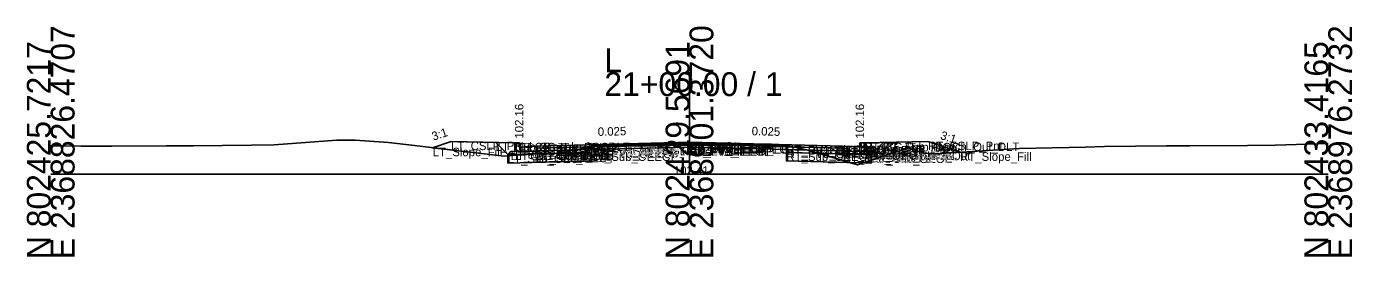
# Model space of a CAD drawing. Extents: x -26 to 8153, y -10 to 9520.
# Drawn here: x 997.2 to 1152.8, y 2490.3 to 2517.3 of the extents above; entities that cross this region are included whole.
import ezdxf

# ---------------------------------------------------------------- set-up
doc = ezdxf.new("R2010")
doc.units = 0
for name, color, linetype in [('Exist CMT Pavement', 7, 'Continuous'), ('Exist Cross Section Cell', 7, 'Continuous'), ('Exist XS Center Line Elevation Label', 7, 'Continuous'), ('Exist XS Ground Line', 7, 'Continuous'), ('Prop CMT Conc Surface', 7, 'Continuous'), ('Prop CMT Concrete Structures', 7, 'Continuous'), ('Prop CMT Pvmt Course 1', 7, 'Continuous'), ('Prop CMT Pvmt Course 1 CG', 7, 'Continuous'), ('Prop CMT Pvmt Course 1 Wedge', 7, 'Continuous'), ('Prop CMT Pvmt Course 2', 7, 'Continuous'), ('Prop CMT Pvmt Course 2 Wedge', 7, 'Continuous'), ('Prop CMT Pvmt Course 3', 7, 'Continuous'), ('Prop CMT Pvmt Course 3 Wedge', 7, 'Continuous'), ('Prop CMT Pvmt Surface', 7, 'Continuous'), ('Prop CMT Pvmt Wedge Surface 1', 7, 'Continuous'), ('Prop CMT Pvmt Wedge Surface 2', 7, 'Continuous'), ('Prop CMT Pvmt Wedge Surface 3', 7, 'Continuous'), ('Prop CMT Shallow Undercut', 7, 'Continuous'), ('Prop CMT Shallow Undercut Boundary', 7, 'Continuous'), ('Prop CMT Slope Grass', 7, 'Continuous'), ('Prop CMT Subgrade Earthwork', 7, 'Continuous'), ('Prop XS Earthwork Shape', 7, 'Continuous'), ('Prop XS Hydro Elevations', 7, 'Continuous'), ('Prop XS SE Text', 7, 'Continuous'), ('Prop XS Side Slope Text', 7, 'Continuous'), ('Prop XS Subgrade Earthwork', 7, 'Continuous'), ('Scratch_Level_2', 7, 'Continuous'), ('Scratch_Level_6', 7, 'Continuous')]:
    doc.layers.add(name, color=color, linetype=linetype)

msp = doc.modelspace()

# ---------------------------------------------------------------- linework, layer by layer
at = {"layer": 'Exist CMT Pavement'}
for p, q in [((1069.64, 2503.31), (1074.61, 2503.41)), ((1074.61, 2503.41), (1075, 2503.41)), ((1075, 2503.41), (1079.57, 2503.41)), ((1079.57, 2503.41), (1086.38, 2503.35)), ((1063.51, 2503.2), (1069.64, 2503.31))]:
    msp.add_line(p, q, dxfattribs=at)
at = {"layer": 'Exist Cross Section Cell'}
for p, q in [((1075, 2500), (1075, 2511.96)), ((1000, 2500), (1075, 2500)), ((1075, 2500), (1150, 2500))]:
    msp.add_line(p, q, dxfattribs=at)
at = {"layer": 'Exist XS Ground Line'}
for p, q in [((1016.71, 2503.33), (1023.59, 2503.4)), ((1023.59, 2503.4), (1026.24, 2503.44)), ((1026.24, 2503.44), (1033.6, 2503.97)), ((1033.6, 2503.97), (1035.76, 2503.99)), ((1035.76, 2503.99), (1039.64, 2503.7)), ((1039.64, 2503.7), (1042.72, 2503.34)), ((1069.64, 2503.31), (1074.61, 2503.41)), ((1074.61, 2503.41), (1075, 2503.41)), ((1075, 2503.41), (1079.57, 2503.41)), ((1079.57, 2503.41), (1086.38, 2503.35)), ((1133.74, 2503.33), (1140.53, 2503.36)), ((1140.53, 2503.36), (1143.75, 2503.41)), ((1143.75, 2503.41), (1150, 2503.57)), ((1000, 2503.32), (1003.56, 2503.26)), ((1003.56, 2503.26), (1007.19, 2503.28)), ((1007.19, 2503.28), (1013.57, 2503.31)), ((1013.57, 2503.31), (1016.71, 2503.33)), ((1042.72, 2503.34), (1049.55, 2502.53)), ((1049.55, 2502.53), (1053.25, 2502.11)), ((1053.25, 2502.11), (1054.73, 2502.22)), ((1054.73, 2502.22), (1057.2, 2502.37)), ((1057.2, 2502.37), (1059.02, 2502.39)), ((1059.02, 2502.39), (1063.51, 2503.2)), ((1063.51, 2503.2), (1069.64, 2503.31)), ((1086.38, 2503.35), (1088.58, 2502.89)), ((1088.58, 2502.89), (1088.89, 2502.82)), ((1088.89, 2502.82), (1090.91, 2502.2)), ((1090.91, 2502.2), (1094.71, 2501.08)), ((1096.79, 2501.78), (1100.77, 2503.08)), ((1100.77, 2503.08), (1101.64, 2502.69)), ((1101.64, 2502.69), (1102.43, 2502.48)), ((1102.43, 2502.48), (1103.7, 2502.38)), ((1103.7, 2502.38), (1105.1, 2502.45)), ((1105.1, 2502.45), (1113.71, 2503)), ((1113.71, 2503), (1121.48, 2503.15)), ((1121.48, 2503.15), (1123.72, 2503.22)), ((1123.72, 2503.22), (1131, 2503.33)), ((1131, 2503.33), (1133.74, 2503.33)), ((1094.71, 2501.08), (1096.79, 2501.78))]:
    msp.add_line(p, q, dxfattribs=at)
at = {"layer": 'Prop CMT Conc Surface'}
for points in [[(1055, 2503.16), (1055, 2503.66), (1054.5, 2503.66)], [(1095, 2503.16), (1095, 2503.66), (1095.5, 2503.66)], [(1057, 2503.29), (1055, 2503.16)], [(1093, 2503.29), (1095, 2503.16)]]:
    msp.add_lwpolyline(points, dxfattribs=at)
at = {"layer": 'Prop CMT Concrete Structures'}
for points in [[(1057, 2503.29), (1055, 2503.16), (1055, 2503.66), (1054.5, 2503.66)], [(1054.5, 2503.66), (1054.5, 2502.64), (1057, 2502.7)], [(1093, 2503.29), (1095, 2503.16), (1095, 2503.66), (1095.5, 2503.66)], [(1095.5, 2503.66), (1095.5, 2502.64), (1093, 2502.7)], [(1057, 2502.7), (1057, 2503.29)], [(1093, 2502.7), (1093, 2503.29)]]:
    msp.add_lwpolyline(points, dxfattribs=at)
at = {"layer": 'Prop CMT Pvmt Course 1'}
for points in [[(1075, 2503.74), (1057, 2503.29)], [(1063.51, 2503.33), (1075, 2503.61)], [(1075, 2503.49), (1075, 2503.74)], [(1075, 2503.74), (1093, 2503.29)], [(1075, 2503.49), (1075, 2503.74)], [(1075, 2503.61), (1075, 2503.49), (1075, 2503.49)], [(1086.38, 2503.33), (1075, 2503.61)], [(1075, 2503.61), (1075, 2503.49), (1075, 2503.49)], [(1057, 2503.29), (1057, 2503.04)], [(1057, 2503.04), (1063.51, 2503.2)], [(1063.51, 2503.2), (1063.51, 2503.33)], [(1086.38, 2503.2), (1086.38, 2503.33)], [(1093, 2503.04), (1086.38, 2503.2)], [(1093, 2503.29), (1093, 2503.04)]]:
    msp.add_lwpolyline(points, dxfattribs=at)
at = {"layer": 'Prop CMT Pvmt Course 1 CG'}
for points in [[(1057, 2502.7), (1054, 2502.63), (1053.66, 2502.29)], [(1053.66, 2502.29), (1057, 2502.38)], [(1057, 2502.38), (1057, 2502.7)], [(1093, 2502.7), (1096, 2502.63), (1096.34, 2502.29)], [(1093, 2502.38), (1093, 2502.7)], [(1096.34, 2502.29), (1093, 2502.38)]]:
    msp.add_lwpolyline(points, dxfattribs=at)
at = {"layer": 'Prop CMT Pvmt Course 1 Wedge'}
for points in [[(1075, 2503.61), (1063.51, 2503.33)], [(1075, 2503.61), (1086.38, 2503.33)]]:
    msp.add_lwpolyline(points, dxfattribs=at)
at = {"layer": 'Prop CMT Pvmt Course 2'}
for points in [[(1063.51, 2503.2), (1057, 2503.04)], [(1057, 2503.04), (1057, 2502.71)], [(1057, 2502.71), (1063.51, 2502.87)], [(1063.51, 2502.87), (1063.51, 2503.2)], [(1086.38, 2502.87), (1086.38, 2503.2)], [(1086.38, 2503.2), (1093, 2503.04)], [(1093, 2502.71), (1086.38, 2502.87)], [(1093, 2503.04), (1093, 2502.71)]]:
    msp.add_lwpolyline(points, dxfattribs=at)
at = {"layer": 'Prop CMT Pvmt Course 2 Wedge'}
for points in [[(1075, 2503.49), (1063.51, 2503.2)], [(1075, 2503.49), (1086.38, 2503.2)]]:
    msp.add_lwpolyline(points, dxfattribs=at)
at = {"layer": 'Prop CMT Pvmt Course 3'}
for points in [[(1063.51, 2502.87), (1057, 2502.71)], [(1057, 2502.71), (1057, 2502.38)], [(1057, 2502.38), (1063.51, 2502.54)], [(1063.51, 2502.54), (1063.51, 2502.87)], [(1086.38, 2502.87), (1093, 2502.71)], [(1086.38, 2502.54), (1086.38, 2502.87)], [(1093, 2502.38), (1086.38, 2502.54)], [(1093, 2502.71), (1093, 2502.38)]]:
    msp.add_lwpolyline(points, dxfattribs=at)
at = {"layer": 'Prop CMT Pvmt Course 3 Wedge'}
for points in [[(1075, 2503.16), (1063.51, 2502.87)], [(1075, 2503.16), (1086.38, 2502.87)]]:
    msp.add_lwpolyline(points, dxfattribs=at)
at = {"layer": 'Prop CMT Pvmt Surface'}
for points in [[(1075, 2503.74), (1057, 2503.29)], [(1075, 2503.74), (1093, 2503.29)]]:
    msp.add_lwpolyline(points, dxfattribs=at)
at = {"layer": 'Prop CMT Pvmt Wedge Surface 1'}
for points in [[(1075, 2503.61), (1063.51, 2503.33)], [(1075, 2503.61), (1086.38, 2503.33)], [(1057, 2503.04), (1057, 2503.29)], [(1063.51, 2503.2), (1057, 2503.04)], [(1063.51, 2503.33), (1063.51, 2503.2)], [(1086.38, 2503.33), (1086.38, 2503.2)], [(1086.38, 2503.2), (1093, 2503.04)], [(1093, 2503.04), (1093, 2503.29)]]:
    msp.add_lwpolyline(points, dxfattribs=at)
at = {"layer": 'Prop CMT Pvmt Wedge Surface 2'}
for points in [[(1075, 2503.49), (1057, 2503.04)], [(1075, 2503.49), (1093, 2503.04)], [(1057, 2503.04), (1057, 2503.29)], [(1093, 2503.04), (1093, 2503.29)]]:
    msp.add_lwpolyline(points, dxfattribs=at)
at = {"layer": 'Prop CMT Pvmt Wedge Surface 3'}
for points in [[(1057, 2502.71), (1057, 2503.29)], [(1075, 2503.16), (1057, 2502.71)], [(1075, 2503.16), (1093, 2502.71)], [(1093, 2502.71), (1093, 2503.29)]]:
    msp.add_lwpolyline(points, dxfattribs=at)
at = {"layer": 'Prop CMT Shallow Undercut'}
for points in [[(1059.02, 2502.39), (1059.27, 2502.43), (1063.51, 2502.54), (1063.51, 2501.54), (1053.66, 2501.29), (1053.66, 2502.14), (1054.73, 2502.22), (1057.2, 2502.37)], [(1086.38, 2502.54), (1086.38, 2501.54), (1093.77, 2501.36), (1090.91, 2502.2), (1090.11, 2502.45)], [(1096.34, 2501.62), (1096.34, 2501.29), (1095.42, 2501.31)]]:
    msp.add_lwpolyline(points, close=True, dxfattribs=at)
at = {"layer": 'Prop CMT Shallow Undercut Boundary'}
for p, q in [((1053.66, 2502.29), (1063.51, 2502.54)), ((1053.66, 2502.29), (1053.66, 2501.29)), ((1063.51, 2502.54), (1063.51, 2501.54)), ((1086.38, 2502.54), (1086.38, 2501.54)), ((1086.38, 2502.54), (1096.34, 2502.29)), ((1096.34, 2502.29), (1096.34, 2501.29)), ((1063.51, 2501.54), (1053.66, 2501.29)), ((1086.38, 2501.54), (1096.34, 2501.29))]:
    msp.add_line(p, q, dxfattribs=at)
at = {"layer": 'Prop CMT Slope Grass'}
for points in [[(1054.5, 2503.66), (1047, 2503.81), (1044.84, 2503.09)], [(1095.5, 2503.66), (1103, 2503.81), (1106.77, 2502.55)]]:
    msp.add_lwpolyline(points, dxfattribs=at)
at = {"layer": 'Prop CMT Subgrade Earthwork'}
for points in [[(1057, 2502.38), (1053.66, 2502.29), (1052.25, 2503.7)], [(1093, 2502.38), (1096.34, 2502.29), (1097.75, 2503.7)], [(1063.51, 2502.54), (1057, 2502.38)], [(1063.51, 2502.54), (1063.53, 2503.2)], [(1086.38, 2502.54), (1086.36, 2503.35)], [(1086.38, 2502.54), (1093, 2502.38)]]:
    msp.add_lwpolyline(points, dxfattribs=at)
at = {"layer": 'Prop XS Earthwork Shape'}
for points in [[(1052.25, 2503.7), (1047, 2503.81), (1044.84, 2503.09), (1049.55, 2502.53), (1053.25, 2502.11), (1053.66, 2502.14), (1053.66, 2502.29)], [(1105.1, 2502.45), (1106.77, 2502.55), (1103, 2503.81), (1097.75, 2503.7), (1096.34, 2502.29), (1096.34, 2501.62), (1096.79, 2501.78), (1100.77, 2503.08), (1101.64, 2502.69), (1102.43, 2502.48), (1103.7, 2502.38)], [(1054.73, 2502.22), (1057.2, 2502.37), (1059.02, 2502.39), (1059.27, 2502.43), (1063.51, 2502.54), (1063.51, 2501.54), (1053.66, 2501.29), (1053.66, 2502.14)], [(1054.73, 2502.22), (1057.2, 2502.37), (1059.02, 2502.39), (1059.27, 2502.43), (1057, 2502.38), (1053.66, 2502.29), (1053.66, 2502.14)], [(1059.27, 2502.43), (1063.51, 2503.2), (1063.53, 2503.2), (1063.51, 2502.54)], [(1086.38, 2503.35), (1088.58, 2502.89), (1088.89, 2502.82), (1090.11, 2502.45), (1086.38, 2502.54), (1086.36, 2503.35)], [(1086.38, 2502.54), (1086.38, 2501.54), (1093.77, 2501.36), (1090.91, 2502.2), (1090.11, 2502.45)], [(1095.42, 2501.31), (1096.34, 2501.62), (1096.34, 2502.29), (1093, 2502.38), (1090.11, 2502.45), (1090.91, 2502.2), (1093.77, 2501.36)], [(1093.77, 2501.36), (1095.42, 2501.31), (1094.71, 2501.08)], [(1095.42, 2501.31), (1096.34, 2501.29), (1096.34, 2501.62)]]:
    msp.add_lwpolyline(points, close=True, dxfattribs=at)
at = {"layer": 'Prop XS Subgrade Earthwork'}
for p, q in [((1053.66, 2502.29), (1063.51, 2502.54)), ((1096.34, 2502.29), (1086.38, 2502.54))]:
    msp.add_line(p, q, dxfattribs=at)
at = {"layer": 'Scratch_Level_6'}
for points in [[(1059.02, 2502.39), (1059.27, 2502.43), (1063.51, 2502.54), (1063.51, 2501.54), (1053.66, 2501.29), (1053.66, 2502.14), (1054.73, 2502.22), (1057.2, 2502.37)], [(1086.38, 2502.54), (1086.38, 2501.54), (1093.77, 2501.36), (1090.91, 2502.2), (1090.11, 2502.45)], [(1096.34, 2501.62), (1096.34, 2501.29), (1095.42, 2501.31)]]:
    msp.add_lwpolyline(points, close=True, dxfattribs=at)

# ---------------------------------------------------------------- texts
at = {"layer": 'Exist Cross Section Cell'}
for s, p in [('E 2368826.4707', (1002.8, 2490)), ('E 2368901.3720', (1077.8, 2490)), ('E 2368976.2732', (1152.8, 2490)), ('N 802425.7217', (1000, 2490)), ('N 802429.5691', (1075, 2490)), ('N 802433.4165', (1150, 2490))]:
    msp.add_text(s, height=2.8, rotation=90, dxfattribs=at).set_placement(p)
for s, p in [('L', (1065, 2511.96)), ('21+00.00 / 1', (1065, 2509.16))]:
    msp.add_text(s, height=2.8, dxfattribs=at).set_placement(p)
at = {"layer": 'Exist XS Center Line Elevation Label'}
msp.add_text('102.41', height=1, dxfattribs=at).set_placement((1073.16, 2499.91))
at = {"layer": 'Prop XS Hydro Elevations'}
for p in [(1055.5, 2504.16), (1095.5, 2504.16)]:
    msp.add_text('102.16', height=1, rotation=90, dxfattribs=at).set_placement(p)
at = {"layer": 'Prop XS SE Text'}
for rotation, p in [(1.4321, (1064.24, 2504.47)), (358.5679, (1082.29, 2504.56))]:
    msp.add_text('0.025', height=1, rotation=rotation, dxfattribs=at).set_placement(p)
at = {"layer": 'Prop XS Side Slope Text'}
for rotation, p in [(18.4349, (1044.93, 2503.91)), (341.5651, (1104.37, 2504.14))]:
    msp.add_text('3:1', height=1, rotation=rotation, dxfattribs=at).set_placement(p)
at = {"layer": 'Scratch_Level_2'}
for s, p in [('LT_CSLP_Pnt', (1047, 2502.81)), ('LT_Sub_Trench_Out_DLT', (1052.25, 2502.7)), ('LT_CG_Top_BOC', (1054.5, 2502.66)), ('LT_CG_Top_Face', (1055, 2502.66)), ('PV1_PGL', (1075, 2502.74)), ('RT_PV1_IEEOP', (1075, 2502.61)), ('LT_PV1_IEEOP', (1075, 2502.61)), ('RT_PV2_IEEOP', (1075, 2502.49)), ('LT_PV2_IEEOP', (1075, 2502.49)), ('PV2_PGL', (1075, 2502.49)), ('RT_PV_IEEOP_EG', (1075, 2502.41)), ('LT_PV_IEEOP_EG', (1075, 2502.41)), ('RT_PV_Sub_Tie_Out', (1086.36, 2502.35)), ('RT_PV_OEEOP_EG', (1086.38, 2502.35)), ('RT_CG_Top_Face', (1095, 2502.66)), ('RT_CG_Top_BOC', (1095.5, 2502.66)), ('RT_Sub_Trench_Out_DLT', (1097.75, 2502.7)), ('RT_CSLP_Pnt', (1103, 2502.81)), ('LT_Slope_Fill', (1044.84, 2502.09)), ('LT_Sub_OEOP', (1053.66, 2501.29)), ('LT_CG1_Shelf_Out', (1054, 2501.63)), ('LT_CG_Bot_BOC', (1054.5, 2501.64)), ('LT_CG_Top_Gut', (1055, 2502.16)), ('LT_PV1_OEOT', (1057, 2502.29)), ('LT_PV2_OEOT', (1057, 2502.04)), ('LT_PV3_OEOT', (1057, 2501.71)), ('LT_CG_Bot_IE', (1057, 2501.7)), ('LT_Sub_OEOT', (1057, 2501.38)), ('LT_PV1_OEEOP', (1063.51, 2502.33)), ('LT_PV2_OEEOP', (1063.51, 2502.2)), ('LT_PV_OEEOP_EG', (1063.51, 2502.2)), ('LT_PV3_OEEOP', (1063.51, 2501.87)), ('LT_Sub_OEEOP', (1063.51, 2501.54)), ('LT_PV_Sub_Tie_Out', (1063.53, 2502.2)), ('RT_PV3_IEEOP', (1075, 2502.16)), ('LT_PV3_IEEOP', (1075, 2502.16)), ('RT_PV1_OEEOP', (1086.38, 2502.33)), ('RT_PV2_OEEOP', (1086.38, 2502.2)), ('RT_PV3_OEEOP', (1086.38, 2501.87)), ('RT_Sub_OEEOP', (1086.38, 2501.54)), ('RT_PV1_OEOT', (1093, 2502.29)), ('RT_PV2_OEOT', (1093, 2502.04)), ('RT_PV3_OEOT', (1093, 2501.71)), ('RT_CG_Bot_IE', (1093, 2501.7)), ('RT_Sub_OEOT', (1093, 2501.38)), ('RT_CG_Top_Gut', (1095, 2502.16)), ('RT_CG_Bot_BOC', (1095.5, 2501.64)), ('RT_CG1_Shelf_Out', (1096, 2501.63)), ('RT_Sub_OEOP', (1096.34, 2501.29)), ('RT_Slope_Fill', (1106.77, 2501.55))]:
    msp.add_text(s, height=1, dxfattribs=at).set_placement(p)

doc.saveas('drawing.dxf')
